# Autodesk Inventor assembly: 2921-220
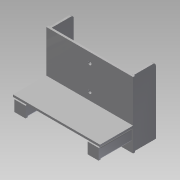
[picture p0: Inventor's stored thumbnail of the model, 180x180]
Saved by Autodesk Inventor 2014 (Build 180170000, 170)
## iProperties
Company: NHTSA/VRTC
Created: 2012-08
Part Number: 2921-220
Document SubType Name: Assembly
Designer: Mike Vanvoorhis
Mass: 23365.3 g
Surface Area: 7512.91 cm^2
Volume: 2972.69 cm^3
Density: 7.86 g/cm^3
Project: CHILD SIDE IMPACT SLED
Description: IMPACTOR STOP FRAME ASSEMBLY
Author: Dave Walker
Title: Impactor Stop Frame Assembly
Subject: Child Side Impact Sled
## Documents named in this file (7)
- B:\VRTC_DWG\BIO\Non-P572\Child Side-Frontal Impact Sled\Side Impact Sled\Impactor_Frame_Assembly.iam
- B:\VRTC_DWG\BIO\Non-P572\Child Side-Frontal Impact Sled\Side Impact Sled\Impactor_Frame_Part1.ipt
- B:\VRTC_DWG\BIO\Non-P572\Child Side-Frontal Impact Sled\Side Impact Sled\Impactor_Frame_Part 2.ipt
- B:\VRTC_DWG\BIO\Non-P572\Child Side-Frontal Impact Sled\Side Impact Sled\Impactor_Frame_Part 3.ipt
- B:\VRTC_DWG\BIO\Non-P572\Child Side-Frontal Impact Sled\Side Impact Sled\Impactor_Frame_Part 4.ipt
- B:\VRTC_DWG\BIO\Non-P572\Child Side-Frontal Impact Sled\Side Impact Sled\Impactor_Frame_Part 5.ipt
- B:\VRTC_DWG\BIO\Non-P572\Child Side-Frontal Impact Sled\Side Impact Sled\Impactor_Frame_Part 6.ipt
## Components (10 placed, 6 different names)
1. Impactor_Frame_Part1:1 — Flush:1, Flush:2, Flush:3, Flush:4, Flush:5, Flush:6, Flush:7, Flush:8, Flush:9, Flush:10, Mate:3, Flush:17, Flush:27, Flush:24, Mate:6
2. Impactor_Frame_Part 2:1 — Flush:1, Flush:2, Flush:3, Flush:12
3. Impactor_Frame_Part 2:2 — Flush:4, Flush:5, Flush:6, Flush:11
4. Impactor_Frame_Part 3:1 — Flush:9, Flush:10, Flush:11
5. Impactor_Frame_Part 3:2 — Flush:7, Flush:8, Flush:12
6. Impactor_Frame_Part 4:1 — Flush:24, Flush:27, Mate:4, Flush:31
7. Impactor_Frame_Part 5:1 — Mate:3, Flush:17, Mate:4, Flush:28, Flush:29, Mate:5, Flush:30
8. Impactor_Frame_Part 5:2 — Mate:6, Flush:30, Flush:31, Flush:32, Flush:33, Mate:7
9. Impactor_Frame_Part 6:1 — Flush:28, Flush:29, Mate:5
10. Impactor_Frame_Part 6:2 — Flush:32, Flush:33, Mate:7
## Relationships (26: Flush 21, Mate 5)
- Flush:1: Impactor_Frame_Part1:1 ↔ Impactor_Frame_Part 2:1
- Flush:2: Impactor_Frame_Part1:1 ↔ Impactor_Frame_Part 2:1
- Flush:3: Impactor_Frame_Part1:1 ↔ Impactor_Frame_Part 2:1
- Flush:4: Impactor_Frame_Part1:1 ↔ Impactor_Frame_Part 2:2
- Flush:5: Impactor_Frame_Part1:1 ↔ Impactor_Frame_Part 2:2
- Flush:6: Impactor_Frame_Part1:1 ↔ Impactor_Frame_Part 2:2
- Flush:7: Impactor_Frame_Part1:1 ↔ Impactor_Frame_Part 3:2
- Flush:8: Impactor_Frame_Part1:1 ↔ Impactor_Frame_Part 3:2
- Flush:9: Impactor_Frame_Part1:1 ↔ Impactor_Frame_Part 3:1
- Flush:10: Impactor_Frame_Part1:1 ↔ Impactor_Frame_Part 3:1
- Flush:11: Impactor_Frame_Part 2:2 ↔ Impactor_Frame_Part 3:1
- Flush:12: Impactor_Frame_Part 2:1 ↔ Impactor_Frame_Part 3:2
- Mate:3: Impactor_Frame_Part1:1 ↔ Impactor_Frame_Part 5:1
- Flush:17: Impactor_Frame_Part1:1 ↔ Impactor_Frame_Part 5:1
- Flush:24: Impactor_Frame_Part1:1 ↔ Impactor_Frame_Part 4:1
- Flush:27: Impactor_Frame_Part1:1 ↔ Impactor_Frame_Part 4:1
- Mate:4: Impactor_Frame_Part 4:1 ↔ Impactor_Frame_Part 5:1
- Flush:28: Impactor_Frame_Part 5:1 ↔ Impactor_Frame_Part 6:1
- Flush:29: Impactor_Frame_Part 5:1 ↔ Impactor_Frame_Part 6:1
- Mate:5: Impactor_Frame_Part 5:1 ↔ Impactor_Frame_Part 6:1
- Mate:6: Impactor_Frame_Part1:1 ↔ Impactor_Frame_Part 5:2
- Flush:30: Impactor_Frame_Part 5:1 ↔ Impactor_Frame_Part 5:2
- Flush:31: Impactor_Frame_Part 4:1 ↔ Impactor_Frame_Part 5:2
- Flush:32: Impactor_Frame_Part 5:2 ↔ Impactor_Frame_Part 6:2
- Flush:33: Impactor_Frame_Part 5:2 ↔ Impactor_Frame_Part 6:2
- Mate:7: Impactor_Frame_Part 5:2 ↔ Impactor_Frame_Part 6:2
